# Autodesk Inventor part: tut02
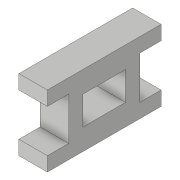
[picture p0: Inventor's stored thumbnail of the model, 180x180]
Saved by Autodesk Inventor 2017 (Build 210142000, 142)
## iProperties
Created: 2015-02
Part Number: tut02
Material: Generic
Document SubType Name: Modeling
Designer: Sandeep
Density: 1 g/cm^3
Appearance: Default
Author: Sandeep
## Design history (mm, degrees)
sketch "Sketch1"
  geometry: L1 (-40, -25)-(40, -25); L2 (40, -25)-(40, -15); L3 (40, -15)-(25, -15); L4 (25, -15)-(25, 15); L5 (25, 15)-(40, 15); L6 (40, 15)-(40, 25); L7 (40, 25)-(-40, 25); L8 (-40, 25)-(-40, 15); L9 (-40, 15)-(-25, 15); L10 (-25, 15)-(-25, -15); L11 (-25, -15)-(-40, -15); L12 (-40, -15)-(-40, -25); L13 (-15, -10)-(15, -10); L14 (15, -10)-(15, 10); L15 (15, 10)-(-15, 10); L16 (-15, 10)-(-15, -10)
  constraints: 32 end point, 7 perpendicular, 3 horizontal, 2 parallel, 2 point on line, 1 vertical
  dimensions: "d0" = 80 distance of L1.start L1.end; "d1" = 10 distance of L1.end L2.end; "d2" = 15 distance of L2.end L3.end; "d3" = 30 distance of L3.end L4.end; "d4" = 15 distance of L4.end L5.end; "d5" = 10 distance of L5.end L6.end; "d6" = 80 distance of L6.end L7.end; "d7" = 10 distance of L7.end L8.end; "d8" = 15 distance of L8.end L9.end; "d9" = 30 distance of L9.end L10.end; "d10" = 15 distance of L10.end L11.end; "d12" = 30 distance of L15.end L14.end; "d13" = 20 distance of L14.end L13.end
extrude "Extrusion1" new body sketch "Sketch1" distance "d14" = 20; taper "d15" = 0 deg
body "Solid1"
